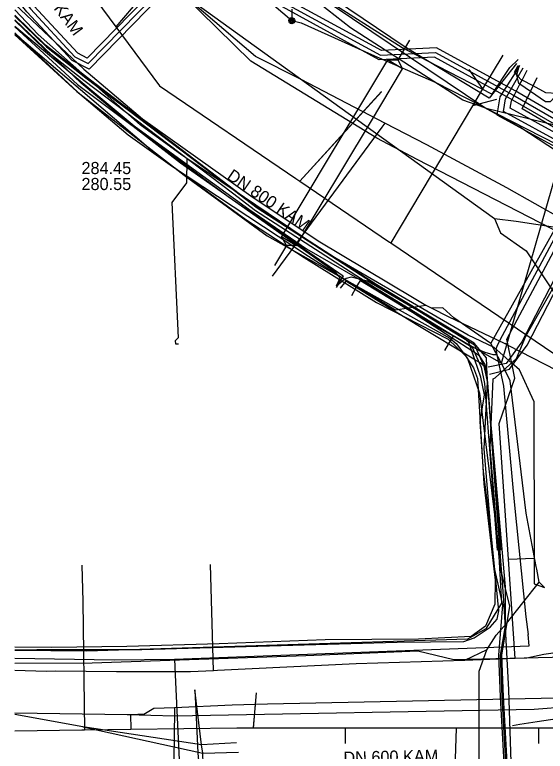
# Model space of a CAD drawing. Extents: x -599854 to -599675, y -1160809 to -1160543.
# Drawn here: x -599854.37 to -599819.46, y -1160620.79 to -1160572.33 of the extents above; entities that cross this region are included whole.
import ezdxf

# ---------------------------------------------------------------- set-up
doc = ezdxf.new("R2010")
doc.units = 0
for name, color, linetype in [('BKOM-ODVODNENI_trasa sítě', 7, 'Continuous'), ('BVK-JEDNOTNA_popisy', 7, 'Continuous'), ('BVK-JEDNOTNA_trasa sítě', 7, 'Continuous'), ('BVK-KANALIZACE_ vyřazená trasa sítě', 7, 'Continuous'), ('BVK-VODOVOD_trasa sítě', 7, 'Continuous'), ('BVK-VODOVOD_trasa zrušené sítě', 7, 'Continuous'), ('CETIN_kabel podzemní', 7, 'Continuous'), ('CETIN_kabel podzemní neprovozovaný', 7, 'Continuous'), ('DESTOVA_trasa neprovozované sítě', 7, 'Continuous'), ('DPMB_kabel', 7, 'Continuous'), ('DPMB_kyneta', 7, 'Continuous'), ('DPMB_trolejové vedení-nosné lano', 7, 'Continuous'), ('DSP-JEDNOTNA-BVK_trasa sítě', 7, 'Continuous'), ('EON-NN_kabel', 7, 'Continuous'), ('EON-NN_kabel zrušené sítě', 7, 'Continuous'), ('EON-SDEL_kabel', 7, 'Continuous'), ('EON-VN_kabel', 7, 'Continuous'), ('EON-VN_kabel zrušené sítě', 7, 'Continuous'), ('INNOGY-STL_trasa sítě', 7, 'Continuous'), ('JEDNOTNA_trasa neprovozované sítě', 7, 'Continuous'), ('TSB_kabel VO', 7, 'Continuous'), ('TSB_lampy VO', 7, 'Continuous')]:
    doc.layers.add(name, color=color, linetype=linetype)

msp = doc.modelspace()

# ---------------------------------------------------------------- linework, layer by layer
at = {"layer": 'BKOM-ODVODNENI_trasa sítě'}
for points in [[(-599830.236, -1160577.373), (-599835.609, -1160583.276)], [(-599838.489, -1160616.937), (-599838.68, -1160619.232)]]:
    msp.add_lwpolyline(points, dxfattribs=at)
at = {"layer": 'BVK-JEDNOTNA_popisy'}
msp.add_line((-599849.981, -1160582.94), (-599849.981, -1160582.94), dxfattribs=at)
at = {"layer": 'BVK-JEDNOTNA_trasa sítě'}
for points in [[(-599854.3744, -1160564.1398), (-599853.077, -1160565.893), (-599852.994, -1160566.006), (-599847.723, -1160573.128), (-599844.85, -1160577.01)], [(-599844.85, -1160577.01), (-599835.874, -1160583.097), (-599835.609, -1160583.276), (-599829.7, -1160587.283), (-599829.617, -1160587.34), (-599815.952, -1160596.606), (-599815.795, -1160596.712), (-599812.592, -1160598.884), (-599812.551, -1160598.912), (-599810.515, -1160600.293), (-599810.225, -1160600.489), (-599809, -1160601.32)], [(-599839.75, -1160619.26), (-599846.744, -1160619.353), (-599849.789, -1160619.394), (-599849.953, -1160619.396), (-599854.3744, -1160619.4563)], [(-599814.34, -1160619.27), (-599818.89, -1160619.268), (-599819.88, -1160619.268), (-599825.3, -1160619.266), (-599832.61, -1160619.263), (-599837.36, -1160619.261), (-599838.683, -1160619.26), (-599839.75, -1160619.26)]]:
    msp.add_lwpolyline(points, dxfattribs=at)
at = {"layer": 'BVK-KANALIZACE_ vyřazená trasa sítě'}
msp.add_line((-599853.08, -1160563.93), (-599822.796, -1160585.73), dxfattribs=at)
for points in [[(-599822.796, -1160585.73), (-599821.384, -1160585.908), (-599811.025, -1160587.485), (-599805.422, -1160587.8), (-599801.54, -1160587.634), (-599791.243, -1160584.941), (-599789.279, -1160584.062), (-599787.442, -1160583.059), (-599785.884, -1160582.21), (-599784.335, -1160581.226), (-599782.303, -1160579.92), (-599781.529, -1160579.068)], [(-599822.796, -1160585.73), (-599822.412, -1160586.686), (-599820.726, -1160587.859), (-599816.486, -1160594.211)]]:
    msp.add_lwpolyline(points, dxfattribs=at)
at = {"layer": 'BVK-VODOVOD_trasa sítě'}
msp.add_line((-599846.98, -1160618.37), (-599846.27, -1160618.35), dxfattribs=at)
for points in [[(-599815.98, -1160587.08), (-599816.39, -1160586.87), (-599822, -1160583.72), (-599827.25, -1160580.9), (-599830.01, -1160579.46), (-599835.52, -1160576.6), (-599838.52, -1160575.08), (-599843.3, -1160570.99)], [(-599830.01, -1160579.46), (-599830.22, -1160579.72), (-599837.43, -1160589.52)], [(-599846.27, -1160618.35), (-599845.87, -1160618.34), (-599845.21, -1160617.96), (-599843.85, -1160617.9), (-599840.06, -1160617.72), (-599837.75, -1160617.67), (-599817.61, -1160617.24), (-599816.89, -1160616.73), (-599813.48, -1160603.89), (-599810.07, -1160591.05), (-599810.46, -1160590.14), (-599814.51, -1160587.87), (-599814.93, -1160587.64)], [(-599854.3744, -1160618.2588), (-599846.98, -1160618.37)], [(-599843.85, -1160617.9), (-599843.85, -1160618.1), (-599844.02, -1160629.49), (-599843.44, -1160635.17), (-599842.84, -1160635.66), (-599840.428, -1160636.038)]]:
    msp.add_lwpolyline(points, dxfattribs=at)
at = {"layer": 'BVK-VODOVOD_trasa zrušené sítě'}
msp.add_line((-599816.383, -1160587.777), (-599827.89, -1160581.85), dxfattribs=at)
for points in [[(-599827.89, -1160581.85), (-599830.538, -1160580.457), (-599838.842, -1160575.375), (-599843.3, -1160570.99)], [(-599846.98, -1160618.37), (-599843.851, -1160618.458), (-599820.2, -1160618.014), (-599817.921, -1160617.85)]]:
    msp.add_lwpolyline(points, dxfattribs=at)
at = {"layer": 'CETIN_kabel podzemní'}
for points in [[(-599823.44, -1160578.45), (-599824.88, -1160577.95), (-599832.27, -1160573.2), (-599840.85, -1160566.46)], [(-599854.3744, -1160571.6429), (-599849.83, -1160575.91)], [(-599843.04, -1160581.78), (-599843.38, -1160581.56), (-599846.12, -1160579.58), (-599852.83, -1160573.64), (-599854.3744, -1160572.0135)], [(-599852.1, -1160575.66), (-599854.3744, -1160573.5157)], [(-599852.1, -1160575.66), (-599850.24, -1160577.4), (-599846.9, -1160580.23), (-599843.99, -1160582.32), (-599835.05, -1160588.21), (-599832.33, -1160589.94), (-599829.32, -1160591.75), (-599827.31, -1160591.43)], [(-599849.83, -1160575.91), (-599845.97, -1160579.18), (-599838.83, -1160584.25), (-599834.41, -1160587.2), (-599828.09, -1160590.97)], [(-599823.44, -1160578.45), (-599818.67, -1160579.62), (-599818.39, -1160579.19)], [(-599823.04, -1160593.97), (-599816.62, -1160582.5), (-599815.69, -1160581.06), (-599814.4, -1160581.07)], [(-599843.04, -1160581.78), (-599843.08, -1160583.39), (-599844.03, -1160584.68), (-599843.62, -1160593.58), (-599843.81, -1160593.79), (-599843.8, -1160593.99), (-599843.6, -1160593.98)], [(-599821.67, -1160595.25), (-599822.83, -1160594.22), (-599824.54, -1160593.42), (-599833.89, -1160587.97), (-599843.04, -1160581.78)], [(-599828.09, -1160590.97), (-599827.31, -1160591.43)], [(-599827.31, -1160591.43), (-599826.92, -1160591.63)], [(-599826.21, -1160591.61), (-599826.92, -1160591.63)], [(-599825.47, -1160592.27), (-599826.21, -1160591.61)], [(-599823.04, -1160593.97), (-599825.47, -1160592.27)], [(-599819.87, -1160609.67), (-599820.01, -1160608.81), (-599820.06, -1160608.62), (-599820.72, -1160605.13), (-599821.76, -1160596.42), (-599822.24, -1160595.48), (-599823.04, -1160593.97)], [(-599820.22, -1160597.76), (-599821.16, -1160595.7), (-599821.67, -1160595.25)], [(-599820.22, -1160597.76), (-599820.19, -1160608.08)], [(-599821.87, -1160608.14), (-599820.19, -1160608.08)], [(-599820.19, -1160608.08), (-599820.19, -1160609.77)], [(-599821.43, -1160614.69), (-599821.87, -1160608.14)], [(-599823.3, -1160614.12), (-599822.7, -1160613.14), (-599822.01, -1160612.37), (-599819.87, -1160609.67)], [(-599820.19, -1160609.77), (-599819.5, -1160610.01)], [(-599819.87, -1160609.67), (-599819.5, -1160610.01)], [(-599823.3, -1160614.12), (-599824.779, -1160614.804)], [(-599824.21, -1160627.1), (-599823.81, -1160626.82), (-599823.81, -1160615.51), (-599823.3, -1160614.12)], [(-599815.12, -1160614.04), (-599816.71, -1160614), (-599819.55, -1160614.42), (-599820.67, -1160614.66), (-599821.43, -1160614.69)], [(-599824.779, -1160614.804), (-599831.9, -1160615.03), (-599841.04, -1160615.48)], [(-599821.43, -1160614.69), (-599824.779, -1160614.804)], [(-599841.29, -1160615.5), (-599842.8, -1160615.57), (-599847.67, -1160615.56), (-599851.67, -1160615.52), (-599852.3, -1160615.54), (-599854.3744, -1160615.4716)], [(-599841.04, -1160615.48), (-599841.29, -1160615.5)]]:
    msp.add_lwpolyline(points, dxfattribs=at)
at = {"layer": 'CETIN_kabel podzemní neprovozovaný'}
for points in [[(-599823.44, -1160578.45), (-599839.59, -1160567.57), (-599842.33, -1160565.09)], [(-599816.25, -1160582.92), (-599821.13, -1160579.72), (-599823.44, -1160578.45)], [(-599821.91, -1160594.08), (-599821.99, -1160593.67), (-599816.34, -1160583.08), (-599816.25, -1160582.92)], [(-599826.92, -1160591.63), (-599825.86, -1160592.18), (-599822.12, -1160593.97)], [(-599821.91, -1160594.08), (-599822.12, -1160593.97)], [(-599807.11, -1160601), (-599813.11, -1160598.61), (-599821.91, -1160594.08)], [(-599821.71, -1160595.06), (-599821.91, -1160594.08)], [(-599821.67, -1160595.25), (-599821.71, -1160595.06)], [(-599821.47, -1160596.25), (-599821.67, -1160595.25)], [(-599821.87, -1160608.14), (-599822.5, -1160599.22), (-599821.47, -1160596.25)], [(-599841.29, -1160615.5), (-599841.48, -1160608.5)]]:
    msp.add_lwpolyline(points, dxfattribs=at)
at = {"layer": 'DESTOVA_trasa neprovozované sítě'}
for p, q in [((-599843.62, -1160568.32), (-599847.723, -1160573.128)), ((-599824.484, -1160575.924), (-599823.583, -1160577.216)), ((-599830.23, -1160577.4), (-599835.609, -1160583.276)), ((-599822.662, -1160577.917), (-599824.249, -1160578.333)), ((-599838.49, -1160616.93), (-599838.683, -1160619.26)), ((-599825.49, -1160624.76), (-599825.3, -1160619.266))]:
    msp.add_line(p, q, dxfattribs=at)
at = {"layer": 'DPMB_kabel'}
for points in [[(-599854.3744, -1160570.8811), (-599853.98, -1160571.11), (-599853.34, -1160571.94), (-599850.41, -1160575.09), (-599849.54, -1160575.55), (-599841.94, -1160567.75), (-599841.46, -1160567.86), (-599836.83, -1160571.43), (-599830.31, -1160574.99), (-599826.68, -1160574.81), (-599821.59, -1160577.6), (-599817.92, -1160579.72), (-599816.48, -1160579.55), (-599815.751, -1160578.652), (-599810.91, -1160571.26), (-599805.31, -1160565.16), (-599798.95, -1160559.8), (-599795.69, -1160558.33), (-599784.88, -1160555), (-599775.62, -1160554.42), (-599765.57, -1160554.12), (-599753.796, -1160555.833), (-599746.11, -1160559.64), (-599743.15, -1160562.7)], [(-599854.3744, -1160570.8811), (-599853.98, -1160571.11), (-599853.34, -1160571.94), (-599850.41, -1160575.09), (-599849.54, -1160575.55), (-599841.94, -1160567.75), (-599841.46, -1160567.86), (-599836.83, -1160571.43), (-599830.31, -1160574.99), (-599826.68, -1160574.81), (-599821.59, -1160577.6), (-599817.92, -1160579.72), (-599816.48, -1160579.55), (-599815.751, -1160578.652), (-599810.91, -1160571.26), (-599805.31, -1160565.16), (-599798.95, -1160559.8), (-599795.69, -1160558.33), (-599784.88, -1160555), (-599775.62, -1160554.42), (-599765.57, -1160554.12), (-599753.796, -1160555.833), (-599746.11, -1160559.64), (-599743.15, -1160562.7)], [(-599799.111, -1160559.544), (-599805.518, -1160564.943), (-599811.148, -1160571.075), (-599815.994, -1160578.475), (-599816.636, -1160579.266), (-599817.856, -1160579.41), (-599821.443, -1160577.339), (-599826.61, -1160574.506), (-599830.24, -1160574.686), (-599836.666, -1160571.178), (-599841.329, -1160567.582), (-599842.037, -1160567.42), (-599849.598, -1160575.18), (-599850.225, -1160574.849), (-599853.111, -1160571.746), (-599853.778, -1160570.88), (-599854.3744, -1160570.5339)], [(-599799.111, -1160559.544), (-599805.518, -1160564.943), (-599811.148, -1160571.075), (-599815.994, -1160578.475), (-599816.636, -1160579.266), (-599817.856, -1160579.41), (-599821.443, -1160577.339), (-599826.61, -1160574.506), (-599830.24, -1160574.686), (-599836.666, -1160571.178), (-599841.329, -1160567.582), (-599842.037, -1160567.42), (-599849.598, -1160575.18), (-599850.225, -1160574.849), (-599853.111, -1160571.746), (-599853.778, -1160570.88), (-599854.3744, -1160570.5339)]]:
    msp.add_lwpolyline(points, dxfattribs=at)
at = {"layer": 'DPMB_kyneta'}
msp.add_lwpolyline([(-599775.601, -1160554.719), (-599784.826, -1160555.297), (-599795.584, -1160558.611), (-599798.789, -1160560.056), (-599805.102, -1160565.377), (-599810.672, -1160571.445), (-599815.508, -1160578.829), (-599816.324, -1160579.834), (-599817.984, -1160580.03), (-599821.737, -1160577.861), (-599826.75, -1160575.114), (-599830.38, -1160575.294), (-599836.994, -1160571.682), (-599841.591, -1160568.138), (-599841.843, -1160568.08), (-599849.482, -1160575.92), (-599850.595, -1160575.331), (-599853.569, -1160572.134), (-599854.182, -1160571.34), (-599854.3744, -1160571.2283)], dxfattribs=at)
at = {"layer": 'DPMB_trolejové vedení-nosné lano'}
for points in [[(-599828.39, -1160574), (-599829.17, -1160575.301)], [(-599829.836, -1160575.288), (-599831.94, -1160578.8)], [(-599828.845, -1160575.883), (-599829.836, -1160575.288), (-599829.17, -1160575.301), (-599828.845, -1160575.883)], [(-599830.96, -1160579.42), (-599828.845, -1160575.883)], [(-599831.94, -1160578.8), (-599833.68, -1160581.69)], [(-599832.71, -1160582.33), (-599830.96, -1160579.42)], [(-599833.68, -1160581.69), (-599836.819, -1160586.927)], [(-599835.828, -1160587.522), (-599832.71, -1160582.33)], [(-599835.828, -1160587.522), (-599836.494, -1160587.509), (-599836.819, -1160586.927), (-599835.828, -1160587.522)], [(-599836.494, -1160587.509), (-599837.28, -1160588.82)], [(-599841.968, -1160626.344), (-599841.918, -1160623.101), (-599841.952, -1160622.311), (-599841.994, -1160620.91), (-599842.088, -1160620.363), (-599842.528, -1160616.745)], [(-599842.528, -1160616.745), (-599842.355, -1160620.405), (-599842.326, -1160620.901), (-599842.2, -1160622.364), (-599842.157, -1160623.068), (-599841.968, -1160626.344)], [(-599839.777, -1160620.23), (-599842.088, -1160620.363), (-599849.894, -1160619.17), (-599854.3744, -1160618.3555)], [(-599819.99, -1160618.83), (-599818.68, -1160618.62)], [(-599849.894, -1160619.17), (-599841.994, -1160620.91), (-599839.648, -1160620.839)], [(-599821.613, -1160619.079), (-599821.14, -1160619.01)], [(-599821.14, -1160619.01), (-599819.99, -1160618.83)]]:
    msp.add_lwpolyline(points, dxfattribs=at)
at = {"layer": 'DSP-JEDNOTNA-BVK_trasa sítě'}
msp.add_line((-599830.23, -1160577.4), (-599835.609, -1160583.276), dxfattribs=at)
msp.add_line((-599830.23, -1160577.4), (-599835.609, -1160583.276), dxfattribs=at)
at = {"layer": 'EON-NN_kabel'}
for points in [[(-599821.363, -1160575.54), (-599823.141, -1160577.829), (-599827.207, -1160575.361), (-599828.753, -1160574.423), (-599835.09, -1160570.128), (-599839.903, -1160566.27), (-599844.158, -1160562.552), (-599845.457, -1160561.284), (-599847.509, -1160559.388), (-599849.071, -1160557.708), (-599849.343, -1160557.415), (-599852.072, -1160554.48), (-599851.727, -1160553.718), (-599851.817, -1160553.617)], [(-599796.78, -1160553.49), (-599801.45, -1160556.33), (-599804.8, -1160558.95), (-599806.9, -1160560.72), (-599808.2, -1160561.99), (-599809.4, -1160563.31), (-599811.2, -1160565.43), (-599811.8, -1160566.46), (-599812.69, -1160567.72), (-599814.26, -1160570.12), (-599817.09, -1160574.82), (-599818.695, -1160577.517), (-599818.81, -1160577.71), (-599819.13, -1160578.07), (-599819.44, -1160578.07), (-599820.432, -1160577.383), (-599821.126, -1160576.901), (-599821.2, -1160576.85), (-599821.285, -1160576.478), (-599821.33, -1160576.28), (-599821.329, -1160576.276), (-599821.173, -1160575.723), (-599821.15, -1160575.64)], [(-599833.204, -1160590.175), (-599832.959, -1160589.648), (-599833.224, -1160589.31), (-599836.783, -1160586.818), (-599843.475, -1160582.105), (-599846.577, -1160579.687), (-599846.907, -1160579.413), (-599850.007, -1160576.839), (-599854.3744, -1160572.6617)], [(-599821.961, -1160621.523), (-599822.2, -1160617.195), (-599822.31, -1160614.464), (-599821.801, -1160611.233), (-599822.441, -1160608.569), (-599823.091, -1160600.812), (-599822.879, -1160596.291), (-599822.768, -1160596.219), (-599822.254, -1160595.755), (-599821.35, -1160594.94), (-599820.74, -1160593.48), (-599816.268, -1160585.593), (-599814.94, -1160583.25), (-599815.06, -1160582.78), (-599815.324, -1160582.571), (-599815.78, -1160582.21), (-599816.02, -1160582.02), (-599817.151, -1160581.004), (-599818.08, -1160580.497), (-599821.764, -1160578.485), (-599821.689, -1160577.998), (-599821.126, -1160576.901), (-599820.987, -1160576.629), (-599820.65, -1160575.973)], [(-599854.3744, -1160614.1072), (-599852.91, -1160614.09), (-599846.01, -1160614.08), (-599829.21, -1160613.6), (-599824.81, -1160613.56), (-599824.13, -1160613.32), (-599823.08, -1160612.63), (-599822.62, -1160612.1), (-599822.52, -1160611.55), (-599822.788, -1160608.835), (-599823.004, -1160606.648), (-599823.03, -1160606.38), (-599823.52, -1160602.38), (-599823.75, -1160599.1), (-599823.46, -1160597.34), (-599823.69, -1160596.17), (-599824.09, -1160595.029), (-599824.425, -1160594.075), (-599824.49, -1160593.89), (-599824.98, -1160593.47), (-599831.15, -1160589.85), (-599832.24, -1160589.6), (-599832.57, -1160589.69), (-599832.85, -1160589.88), (-599833.12, -1160590.12)], [(-599822.159, -1160621.557), (-599822.4, -1160617.205), (-599822.51, -1160614.456), (-599822.259, -1160611.16), (-599822.788, -1160608.835), (-599822.839, -1160608.61), (-599823.004, -1160606.648), (-599823.487, -1160600.883), (-599823.269, -1160596.475), (-599823.313, -1160595.743), (-599823.486, -1160595.455), (-599823.748, -1160595.226), (-599824.09, -1160595.029), (-599824.15, -1160594.995), (-599827.964, -1160592.716), (-599831.898, -1160590.277), (-599832.578, -1160589.855), (-599832.966, -1160590.321)]]:
    msp.add_lwpolyline(points, dxfattribs=at)
at = {"layer": 'EON-NN_kabel zrušené sítě'}
for points in [[(-599854.3744, -1160552.0569), (-599853.835, -1160552.73), (-599849.517, -1160557.574), (-599849.343, -1160557.415), (-599848.83, -1160556.948), (-599848.695, -1160557.095), (-599848.56, -1160557.243), (-599849.071, -1160557.708), (-599849.251, -1160557.872), (-599848.608, -1160558.593), (-599844.591, -1160562.612), (-599840.011, -1160566.554), (-599834.335, -1160571.008), (-599828.888, -1160574.494), (-599827.207, -1160575.361), (-599822.963, -1160577.551), (-599821.799, -1160575.81), (-599821.244, -1160575.265)], [(-599854.3744, -1160573.1332), (-599850.251, -1160576.928), (-599846.907, -1160579.413), (-599840.336, -1160584.296), (-599832.764, -1160589.502), (-599833.231, -1160590.274)], [(-599796.77, -1160578.86), (-599802.11, -1160578.86), (-599803.6, -1160578.78), (-599810.5, -1160578.66), (-599815.32, -1160577.78), (-599818.695, -1160577.517), (-599819.43, -1160577.46), (-599820.256, -1160577.019), (-599820.987, -1160576.629), (-599821.06, -1160576.59), (-599821.233, -1160576.388), (-599821.329, -1160576.276), (-599821.443, -1160576.144), (-599821.48, -1160576.1), (-599821.25, -1160575.66)], [(-599821.142, -1160575.674), (-599821.173, -1160575.723), (-599821.443, -1160576.144), (-599822.456, -1160577.727), (-599822.64, -1160578.918), (-599818.31, -1160581.283), (-599815.712, -1160582.703), (-599815.628, -1160583.49), (-599821.004, -1160593.85), (-599822.044, -1160595.279), (-599823.223, -1160595.509)], [(-599823.127, -1160595.977), (-599822.254, -1160595.755), (-599821.815, -1160595.644), (-599820.662, -1160594.059), (-599816.268, -1160585.593), (-599815.218, -1160583.569), (-599815.324, -1160582.571), (-599815.337, -1160582.452), (-599815.78, -1160582.21), (-599818.195, -1160580.891), (-599822.202, -1160578.702), (-599822.073, -1160577.863), (-599821.285, -1160576.478), (-599821.233, -1160576.388), (-599820.908, -1160575.816)], [(-599832.197, -1160590.797), (-599831.898, -1160590.277), (-599831.63, -1160589.811), (-599827.017, -1160592.619), (-599824.425, -1160594.075), (-599822.331, -1160595.251), (-599818.989, -1160583.601), (-599818.31, -1160581.283), (-599818.195, -1160580.891), (-599818.08, -1160580.497), (-599818.01, -1160580.257), (-599820.977, -1160578.512), (-599820.432, -1160577.383), (-599820.256, -1160577.019), (-599819.985, -1160576.457)]]:
    msp.add_lwpolyline(points, dxfattribs=at)
at = {"layer": 'EON-SDEL_kabel'}
for points in [[(-599854.3744, -1160572.4232), (-599852.283, -1160574.442), (-599849.696, -1160576.48), (-599839.919, -1160583.886), (-599838.413, -1160585.045), (-599830.523, -1160590.134), (-599824.114, -1160594.057), (-599823.494, -1160595.452), (-599823.257, -1160596.555), (-599822.417, -1160607.541)], [(-599854.3744, -1160572.7015), (-599852.415, -1160574.593), (-599849.817, -1160576.638), (-599840.039, -1160584.043), (-599838.532, -1160585.207), (-599830.63, -1160590.304), (-599824.272, -1160594.195), (-599823.685, -1160595.514), (-599823.456, -1160596.583), (-599822.616, -1160607.557)], [(-599854.3744, -1160573.6506), (-599850.28, -1160577.38), (-599843.22, -1160582.88), (-599837.76, -1160586.88), (-599831.27, -1160590.51), (-599825.74, -1160593.61), (-599825.33, -1160593.95), (-599824.58, -1160594.94), (-599823.78, -1160597.23), (-599822.55, -1160607.18), (-599822.33, -1160611.05), (-599823.38, -1160612.72), (-599824.58, -1160613.42), (-599849.64, -1160614.21), (-599854.3744, -1160614.1606)]]:
    msp.add_lwpolyline(points, dxfattribs=at)
at = {"layer": 'EON-VN_kabel'}
for points in [[(-599822.06, -1160621.54), (-599822.3, -1160617.2), (-599822.41, -1160614.46), (-599822.106, -1160612.654), (-599822.067, -1160612.419), (-599822.087, -1160609.959), (-599823.257, -1160596.559), (-599823.317, -1160594.899), (-599824.147, -1160593.929), (-599830.537, -1160590.099), (-599838.397, -1160585.039), (-599839.967, -1160583.829), (-599849.397, -1160576.629), (-599852.347, -1160574.339), (-599854.3744, -1160572.3614)], [(-599854.3744, -1160573.5604), (-599844.98, -1160581.56), (-599839.17, -1160585.81), (-599835.32, -1160588.31), (-599830.56, -1160591.26), (-599825.85, -1160593.68), (-599824.7, -1160594.78), (-599824.18, -1160595.55), (-599823.91, -1160596.26), (-599823.5, -1160603.2), (-599822.76, -1160609.52), (-599822.77, -1160611.11), (-599823.39, -1160612.56), (-599824.33, -1160613.24), (-599827.81, -1160613.42), (-599833.94, -1160613.45), (-599840.91, -1160613.71), (-599847, -1160613.9), (-599851.94, -1160613.95), (-599854.3744, -1160613.9461)]]:
    msp.add_lwpolyline(points, dxfattribs=at)
at = {"layer": 'EON-VN_kabel zrušené sítě'}
msp.add_lwpolyline([(-599854.3744, -1160573.0845), (-599850.47, -1160576.35), (-599846.51, -1160579.63), (-599842.88, -1160582.29), (-599838.97, -1160585.12), (-599835.18, -1160587.73), (-599830.37, -1160590.49), (-599823.85, -1160594.71), (-599823.44, -1160595.33), (-599823.31, -1160596), (-599822.8, -1160603.02), (-599822.2, -1160610.87), (-599822.106, -1160612.654), (-599821.89, -1160616.75), (-599821.681, -1160622.866)], dxfattribs=at)
at = {"layer": 'INNOGY-STL_trasa sítě'}
for points in [[(-599814.51, -1160578.96), (-599815.36, -1160580.52), (-599815.66, -1160581.07), (-599815.75, -1160581.24), (-599815.91, -1160581.54), (-599822.3, -1160593.45), (-599822.39, -1160593.61)], [(-599822.64, -1160594.71), (-599822.88, -1160594.7), (-599823.41, -1160594.56), (-599824.25, -1160594.2), (-599825.44, -1160593.5), (-599825.53, -1160593.46), (-599825.85, -1160594), (-599826.09, -1160594.41)], [(-599822.39, -1160593.61), (-599822.64, -1160594.15), (-599822.72, -1160594.33), (-599822.64, -1160594.71), (-599822.2, -1160596.77), (-599821.51, -1160604.37), (-599820.74, -1160611.93), (-599820.59, -1160613.11)], [(-599854.3744, -1160614.6601), (-599847.82, -1160614.78), (-599843.87, -1160614.73), (-599820.52, -1160613.85), (-599820.59, -1160613.11)], [(-599843.87, -1160614.73), (-599843.799, -1160616.23), (-599843.1, -1160631.11), (-599843.1, -1160631.3)]]:
    msp.add_lwpolyline(points, dxfattribs=at)
at = {"layer": 'JEDNOTNA_trasa neprovozované sítě'}
for p, q in [((-599849.968, -1160608.552), (-599849.9, -1160610.93)), ((-599849.9, -1160610.93), (-599849.789, -1160619.394)), ((-599846.757, -1160618.353), (-599846.744, -1160619.353)), ((-599832.61, -1160620.263), (-599832.61, -1160619.263)), ((-599819.88, -1160620.268), (-599819.88, -1160619.268))]:
    msp.add_line(p, q, dxfattribs=at)
msp.add_lwpolyline([(-599822.252, -1160574.983), (-599823.583, -1160577.216), (-599824.249, -1160578.333), (-599829.617, -1160587.34)], dxfattribs=at)
at = {"layer": 'TSB_kabel VO'}
for points in [[(-599854.3744, -1160555.1902), (-599854.04, -1160555.5), (-599849.6, -1160560.93), (-599846.5, -1160564.23), (-599842.34, -1160567.41), (-599836.14, -1160572.72), (-599835.53, -1160572.87), (-599830.9, -1160574.94), (-599826.66, -1160576.79), (-599812.72, -1160583.91), (-599805.44, -1160587.49), (-599799.47, -1160590.02), (-599798.76, -1160590.06), (-599794.55, -1160590.16), (-599791.05, -1160588.25), (-599791.37, -1160587.42), (-599790.5, -1160586.88), (-599785.83, -1160583.3), (-599779.31, -1160578.94), (-599776.23, -1160575.89), (-599774.72, -1160572.96), (-599774.64, -1160569.54), (-599766.89, -1160569.33), (-599766.71, -1160568.47)], [(-599800.51, -1160631.88), (-599801.66, -1160628.63), (-599803.35, -1160621.4), (-599803.6, -1160615.14), (-599817.16, -1160614.58), (-599825.47, -1160614.78), (-599827.84, -1160614.21), (-599835.21, -1160614.5), (-599849.27, -1160614.99), (-599854.3744, -1160615.0219)]]:
    msp.add_lwpolyline(points, dxfattribs=at)
at = {"layer": 'TSB_lampy VO'}
msp.add_line((-599836.14, -1160571.97), (-599836.14, -1160572.72), dxfattribs=at)
msp.add_line((-599836.14, -1160571.97), (-599836.14, -1160572.72), dxfattribs=at)
for radius in [0.2, 0.2, 0.1445, 0.1445, 0.0876, 0.0876]:
    msp.add_circle((-599836.14, -1160572.72), radius, dxfattribs=at)

# ---------------------------------------------------------------- texts
at = {"layer": 'BVK-JEDNOTNA_popisy'}
for s, rotation, p in [('DN 800 KAM', 306.50404, (-599854.175, -1160568.766)), ('DN 800 KAM', 325.85868, (-599840.47, -1160583.096)), ('DN 600 KAM', 1.26051, (-599832.736, -1160621.611))]:
    msp.add_text(s, height=0.8, rotation=rotation, dxfattribs=at).set_placement(p)
for s, p in [('284.45', (-599849.981, -1160582.815)), ('280.55', (-599849.981, -1160583.865))]:
    msp.add_text(s, height=0.8, dxfattribs=at).set_placement(p)

doc.saveas('drawing.dxf')
